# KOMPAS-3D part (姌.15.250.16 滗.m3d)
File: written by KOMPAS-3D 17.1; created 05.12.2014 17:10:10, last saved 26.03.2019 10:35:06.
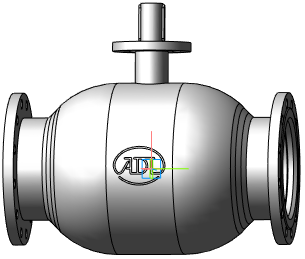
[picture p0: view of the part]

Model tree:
1. Операция без истории:4  (labels: Сталь 20  ГОСТ 1050-88)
